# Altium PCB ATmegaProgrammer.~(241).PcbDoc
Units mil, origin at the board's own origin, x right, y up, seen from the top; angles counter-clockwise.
Board outline 2130 x 2300 mil, 2 copper layers (Top Layer, Bottom Layer); 13 components, 10 nets, 72 pads, 0 vias.
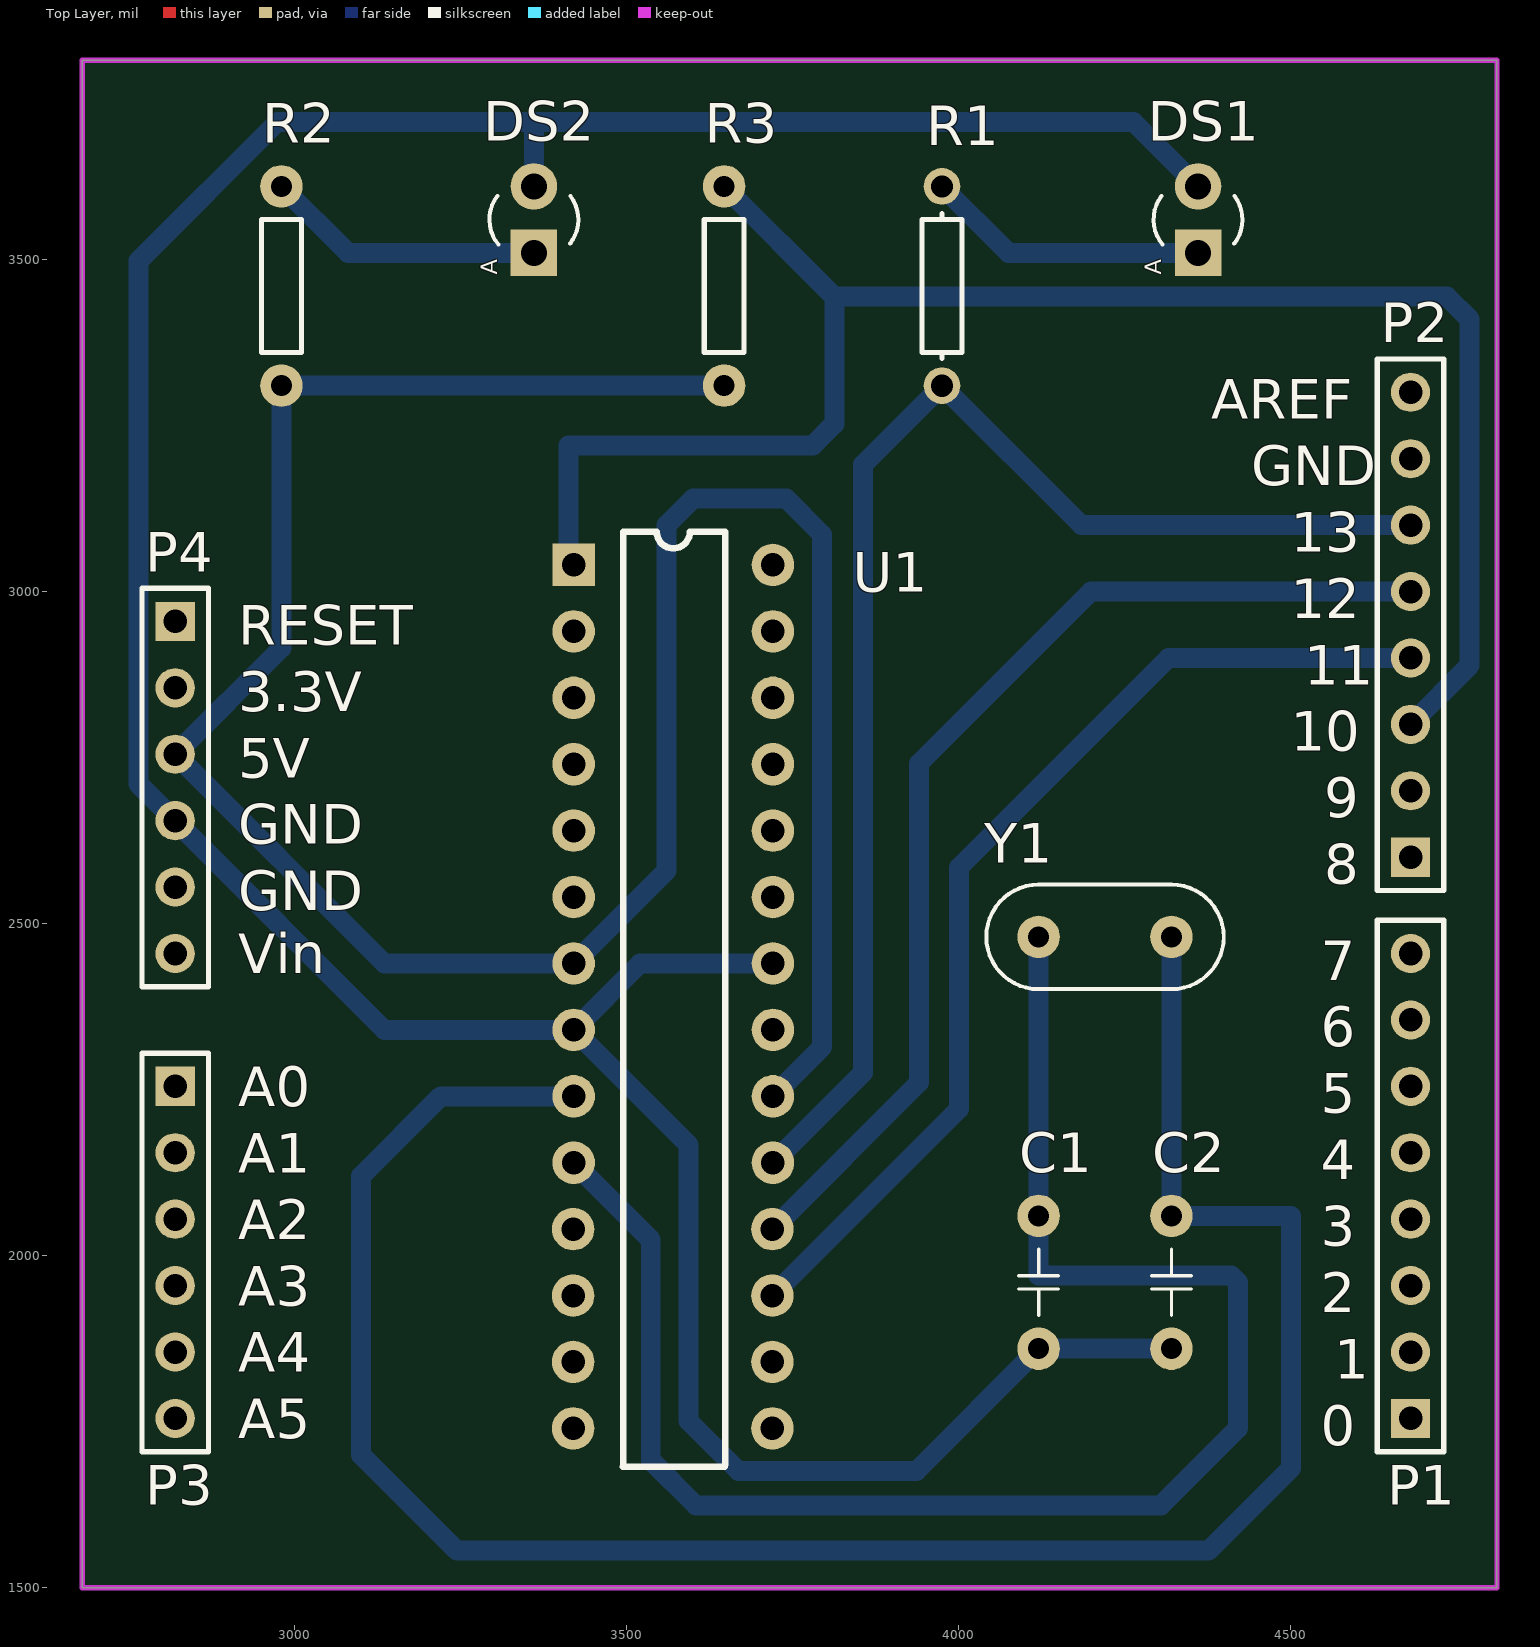
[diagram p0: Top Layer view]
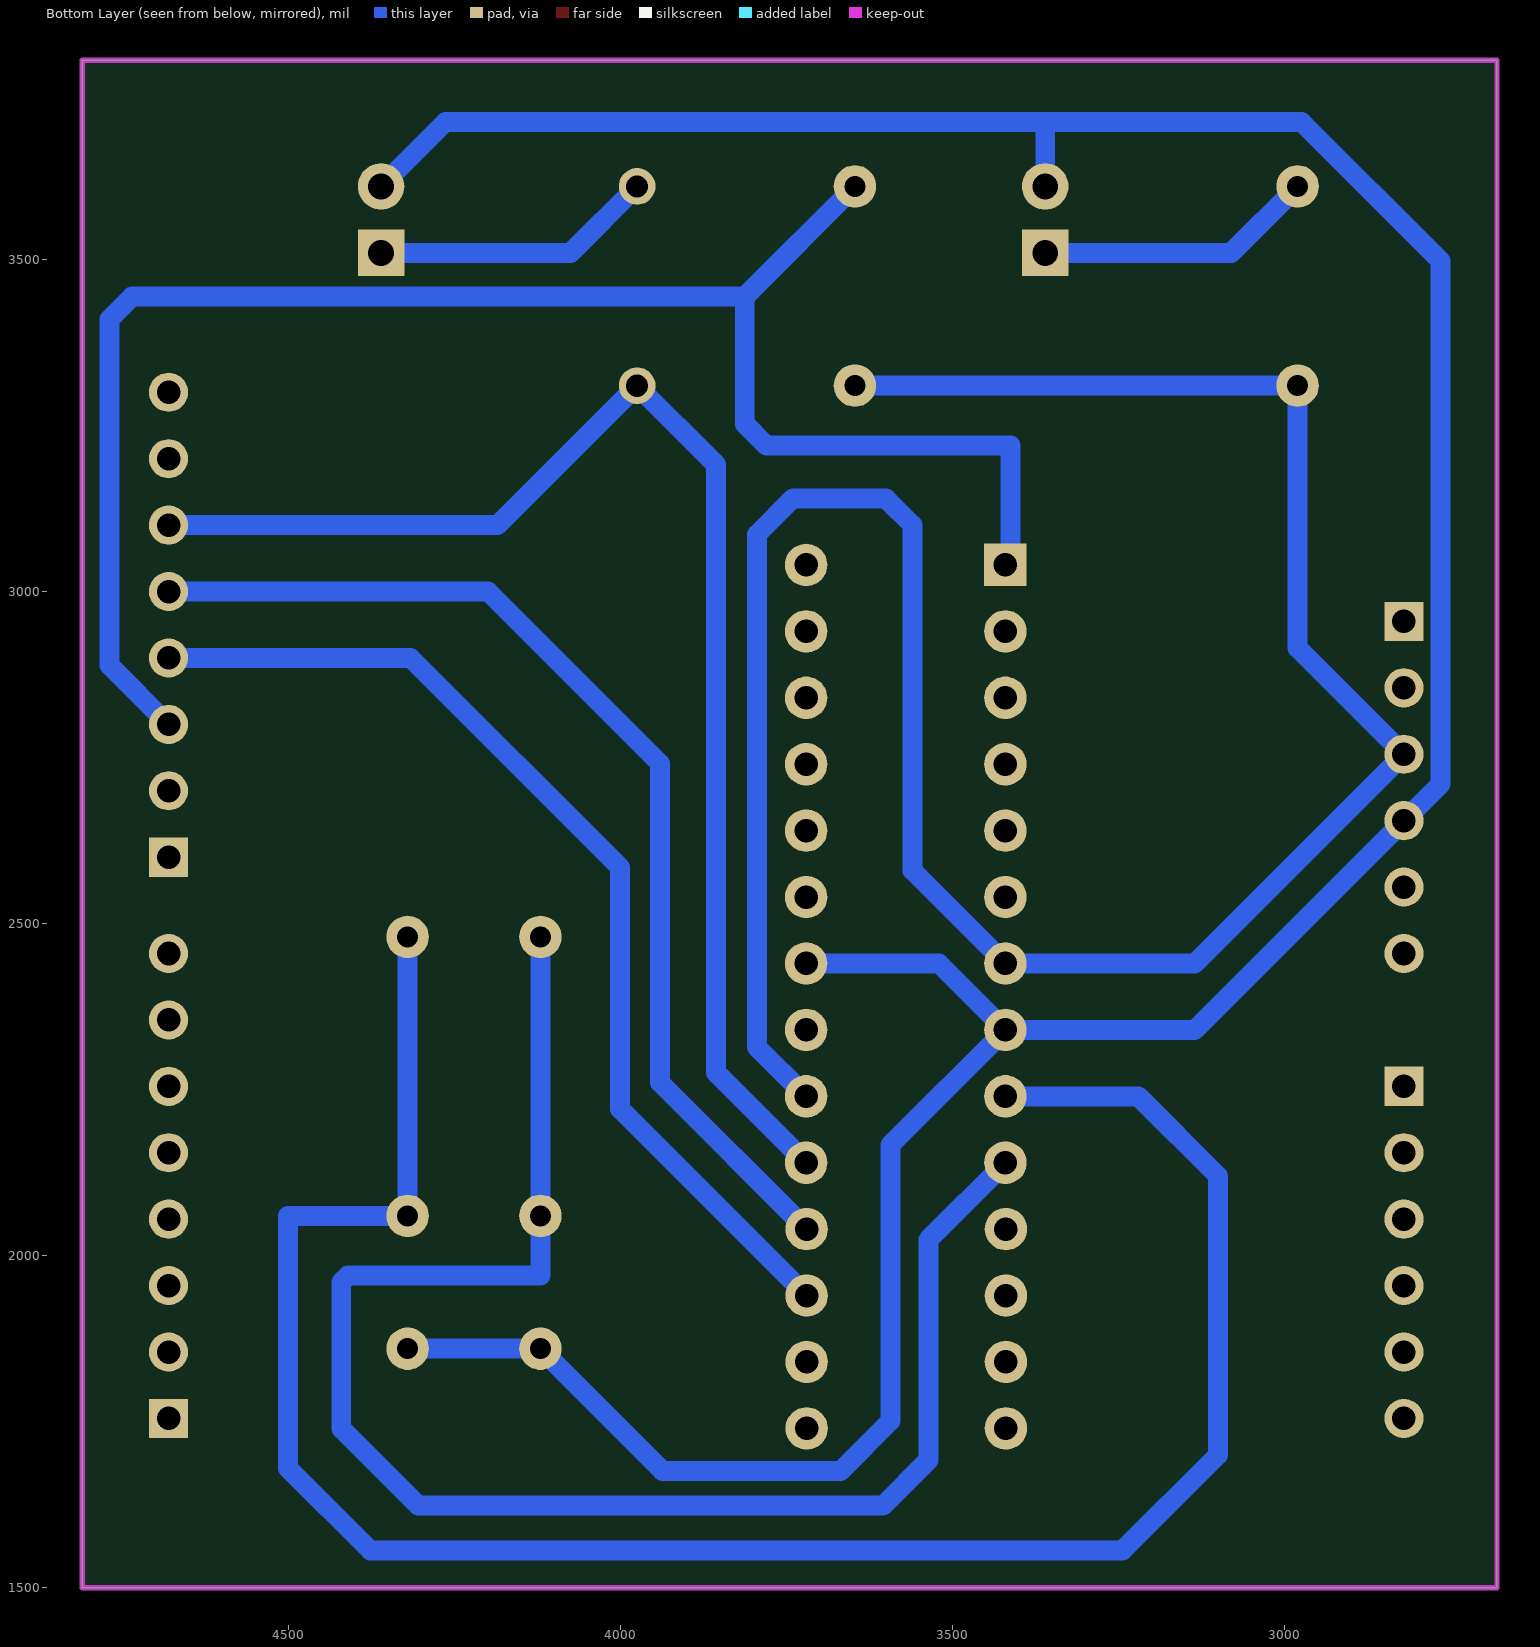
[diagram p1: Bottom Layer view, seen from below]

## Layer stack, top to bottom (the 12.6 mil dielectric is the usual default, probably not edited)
Top Layer: signal copper 1.4
Dielectric: dielectric 12.6, FR-4, Dk 4.8
Bottom Layer: signal copper 1.4

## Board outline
2680,1500 2680,3800 4810,3800 4810,1500

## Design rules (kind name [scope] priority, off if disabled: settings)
Clearance [All] p1: gap=10
PolygonConnect [All] p1: connectstyle=Relief reliefconductorwidth=10 reliefentries=4 polygonreliefangle="90 Angle"
RoutingLayers [All] p1: top layer_v5=FALSE bottom layer_v5=TRUE
RoutingVias [All] p1: holewidth=28 width=50 viastyle="Through Hole" minholewidth=28 minwidth=50 maxholewidth=28 maxwidth=50
SilkscreenOverComponentPads [All] p1: minsilkscreentomaskgap=10
SolderMaskExpansion [All] p1: expansion=4
Width VCC [All] p1: maxlimit=40 minlimit=20 preferedwidth=30
Width GND [InNet('GND')] p2: maxlimit=40 minlimit=20 preferedwidth=30
Width [All] p3: maxlimit=30 minlimit=10 preferedwidth=20
26 further rules are at their usual default settings.

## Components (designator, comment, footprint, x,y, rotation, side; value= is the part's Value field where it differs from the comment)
C1 "20pF" C200 4120,1960 r180 top
C2 "20pF" C200 4320,1960 r180 top
DS1 "LED" LED-3mm_G 4360,3560 r90 top
DS2 "LED" LED-3mm_G 3360.06,3560 r90 top
P1 "Header 8" HDR1X8 4680,1755 r90 top
P2 "Header 8" HDR1X8 4680,2600 r90 top
P3 "Header 6" HDR1X6 2820,2255 r270 top
P4 "Header 6" HDR1X6 2820,2955 r270 top
R1 "Res1" AXIAL-0.3#1 3974.51,3460 r270 top
R2 "220" AXIAL-0.3#2 2980,3460 r270 top
R3 "10k" AXIAL-0.3#2 3646.47,3460 r270 top
U1 "ATmega328" DIP-28 3420,3040 r270 top
Y1 "16MHz" XTAL4-8 4220,2480 r180 top

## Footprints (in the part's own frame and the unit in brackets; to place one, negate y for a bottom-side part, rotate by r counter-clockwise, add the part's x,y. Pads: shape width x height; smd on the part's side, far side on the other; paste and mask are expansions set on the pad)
AXIAL-0.3#1 [mm] "Axial Device, Thru-Hole; 2 Leads; 0.3 in Pin Spacing"
  round 1.4 hole 0.85: 1(-3.81,0) 2(3.81,0)
  silkscreen extent -2.77,-0.76 2.77,0.76
AXIAL-0.3#2 [mm] "0.3\" Resistor; 2 Leads"
  round 1.626 hole 0.8: 1(-3.81,0) 2(3.81,0)
  silkscreen extent -2.54,-0.76 2.54,0.76, body extent -4.1,-1 4.19,1, height 2.19
C200 [mil] "鹅溅筿甧竟"
  round 64 hole 31.5: 1(0,100) 2(0,-100)
  silkscreen extent -30,-50 30,50, body extent -41,-136 39,135, height 354
DIP-28 [mil]
  rect 64x64 hole 35.43: 1(0,0)
  round 64 hole 35.43: 2(100,0) 3(200,0) 4(300,0) 5(400,0) 6(500,0) 7(600,0) 8(700,0) 9(800,0) 10(900,0) 11(1000,-0.79) 12(1100,-0.79) 13(1200,-0.79) 14(1300,-0.79) 15(1300,299.21) 16(1200,299.21) 17(1100,299.21) 18(1000,299.21) 19(900,300) 20(800,300) 21(700,300) 22(600,300) 23(500,300) 24(400,300) 25(300,300) 26(200,300) 27(100,300) 28(0,300)
  silkscreen extent -50,74 1358,228, body extent -53,-5 1358,304, height 209
HDR1X6 [mm] "Connector; Header; 6 Position"
  rect 1.5x1.5 hole 0.9: 1(0,0)
  round 1.5 hole 0.9: 2(2.54,0) 3(5.08,0) 4(7.62,0) 5(10.16,0) 6(12.7,0)
  silkscreen extent -1.27,-1.27 13.97,1.27
HDR1X8 [mm] "Connector; Header; 8 Position"
  rect 1.5x1.5 hole 0.9: 1(0,0)
  round 1.5 hole 0.9: 2(2.54,0) 3(5.08,0) 4(7.62,0) 5(10.16,0) 6(12.7,0) 7(15.24,0) 8(17.78,0)
  silkscreen extent -1.27,-1.27 19.05,1.27
LED-3mm_G [mil] "3mm LED_Green"
  rect 70x70 hole 39: 1(-50,0)
  round 70 hole 39: 2(50,0)
  silkscreen extent -38,-67 35,67, body extent -66,-68 67,66, height 181
XTAL4-8 [mil]
  round 64 hole 31.5: 1(-100,0) 2(100,0)
  silkscreen extent -179,-79 179,79, body extent -178,-80 192,79, height 157

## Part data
C1 C2: library part Cap, "Capacitor"
DS1 DS2: "Typical INFRARED GaAs LED"
P1 P2: "Header, 8-Pin"
P3 P4: "Header, 6-Pin"
R1: "Resistor"
R2 R3: library part Res, "Resistor"
U1: "Arduino"
Y1: library part XTAL, "Crystal Oscillator"

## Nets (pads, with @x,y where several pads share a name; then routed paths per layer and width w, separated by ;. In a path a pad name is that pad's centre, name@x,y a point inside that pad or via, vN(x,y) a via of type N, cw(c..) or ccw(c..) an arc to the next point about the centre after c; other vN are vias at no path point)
GND: C1.1 C2.1 DS1.2 DS2.2 P4.4 U1.8 U1.22 | length 5251.3
  Bottom Layer w30: DS2.2 3360.06,3706.94 ; U1.22 3520,2440 U1.8 ; C2.1 C1.1 3936,1676 3668,1676 3593,1751 3593,2167 U1.8 ; DS1.2 4263,3707 3457.06,3707 2974,3707 2765,3498 2765,2710 P4.4 3135,2340 U1.8
MISO: P2.5 U1.18 | length 1639.7
  Bottom Layer w30: U1.18 3940,2260.79 3940,2741 4199,3000 P2.5
MOSI: P2.4 U1.17 | length 1571.5
  Bottom Layer w30: U1.17 4000,2220.79 4000,2584.49 4315.51,2900 P2.4
NetC1_2: C1.2 U1.10 Y1.2 | length 2490.4
  Bottom Layer w30: U1.10 3536,2024 3536,1692 3604,1624 4304,1624 4420,1740 4420,1960 4410,1970 4120,1970 C1.2 Y1.2
NetC2_2: C2.2 U1.9 Y1.1 | length 3280.7
  Bottom Layer w30: U1.9 3220,2240 3100,2120 3100,1700 3244,1556 4376,1556 4500,1680 4500,2060 C2.2 Y1.1
NetDS1_1: DS1.1 R1.1 | length 426.9
  Bottom Layer w30: R1.1 4074.51,3510 DS1.1
NetDS2_1: DS2.1 R2.1 | length 421.5
  Bottom Layer w30: R2.1 3080,3510 DS2.1
RESET: P2.3 R3.1 U1.1 | length 2629.7
  Bottom Layer w30: U1.1@3412.47,3047.53 3412.47,3220 3780,3220 3812.47,3252.47 3812.47,3444 ; R3.1 3812.47,3444 ; P2.3 4769,2889 4769,3410 4735,3444 3812.47,3444
SCK: P2.6 R1.2 U1.19 | length 2067.9
  Bottom Layer w30: U1.19 3855.5,2275.5 3855.5,3190.99 R1.2 4184.51,3100 P2.6
VCC: P4.3 R2.2 R3.2 U1.7 U1.20 | length 3885.8
  Bottom Layer w30: R3.2 R2.2 2980,2915 P4.3 3135,2440 U1.7 3560,2580 3560,3100 3600,3140 3740,3140 3794,3086 3794,2314 U1.20
pads on no net: P1.1 P1.2 P1.3 P1.4 P1.5 P1.6 P1.7 P1.8 P2.1 P2.2 P2.7 P2.8 P3.1 P3.2 P3.3 P3.4 P3.5 P3.6 P4.1 P4.2 P4.5 P4.6 U1.2 U1.3 U1.4 U1.5 U1.6 U1.11 U1.12 U1.13 U1.14 U1.15 U1.16 U1.21 U1.23 U1.24 U1.25 U1.26 U1.27 U1.28

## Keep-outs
Keep-Out Layer:
  the board outline again, w7.87

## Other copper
Bottom Layer:
  text "AtProgrammer" at 5160,3600 h60 r90

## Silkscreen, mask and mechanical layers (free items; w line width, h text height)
Top Overlay:
  lines w7.87: 0,0 0,200 ; 20,0 35,0 ; 55,0 195,0 ; 2770,2246.75 2770,2255
  text "AREF" at 4380.02,3260 h60
  text "GND" at 4440,3160 h60
  text "13" at 4499.96,3060 h60
  text "12" at 4499.96,2960 h60
  text "RESET" at 2915.05,2920 h60
  text "11" at 4519.95,2860 h60
  text "3.3V" at 2915.05,2820 h60
  text "10" at 4499.96,2760 h60
  text "5V" at 2915.05,2720 h60
  text "9" at 4549.94,2660 h60
  text "GND" at 2915.05,2620 h60
  text "8" at 4549.94,2560 h60
  text "GND" at 2915.05,2520 h60
  text "Vin" at 2915.05,2425 h60
  text "7" at 4544.94,2415 h60
  text "6" at 4544.94,2315 h60
  text "A0" at 2915.05,2225 h60
  text "5" at 4544.94,2215 h60
  text "A1" at 2915.05,2125 h60
  text "4" at 4544.94,2115 h60
  text "A2" at 2915.05,2025 h60
  text "3" at 4544.94,2015 h60
  text "A3" at 2915.05,1925 h60
  text "2" at 4544.94,1915 h60
  text "A4" at 2915.05,1825 h60
  text "1" at 4564.94,1815 h60
  text "A5" at 2915.05,1725 h60
  text "0" at 4544.94,1715 h60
